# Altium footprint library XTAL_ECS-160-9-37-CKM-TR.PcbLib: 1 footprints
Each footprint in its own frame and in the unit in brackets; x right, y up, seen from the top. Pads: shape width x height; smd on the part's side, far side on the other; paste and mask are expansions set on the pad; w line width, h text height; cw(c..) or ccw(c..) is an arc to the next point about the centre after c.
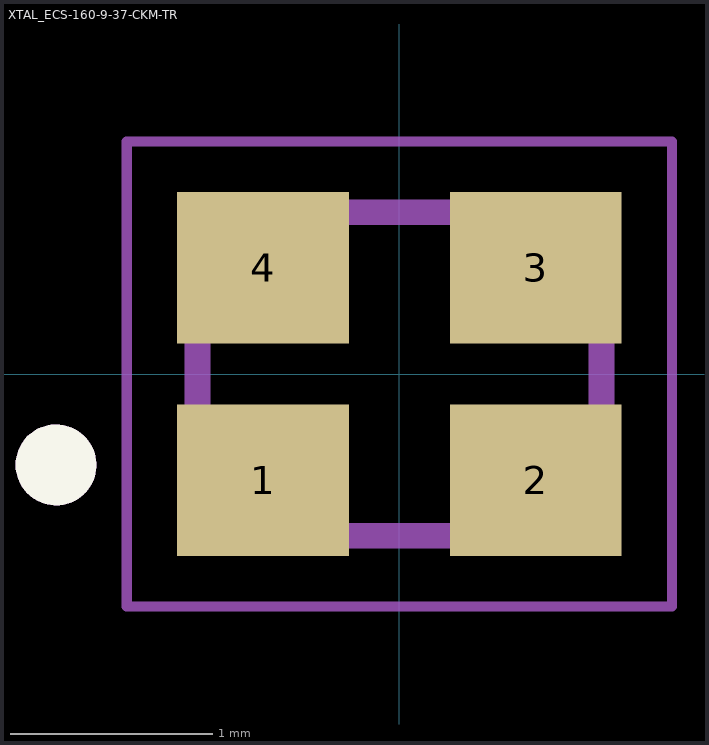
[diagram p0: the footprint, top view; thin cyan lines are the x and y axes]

## XTAL_ECS-160-9-37-CKM-TR [mm]
pads (4):
  rect 0.85x0.75 smd: 1(-0.675,-0.525) 2(0.675,-0.525) 3(0.675,0.525) 4(-0.675,0.525)
Top Overlay:
  circle w0.2: c-1.7,-0.45 r0.1
Mechanical 13:
  circle w0.2: c-1.7,-0.45 r0.1
  lines w0.127: -1,-0.8 -1,0.8 1,0.8 1,-0.8 -1,-0.8
Mechanical 15:
  lines w0.05: -1.35,-1.15 -1.35,1.15 1.35,1.15 1.35,-1.15 -1.35,-1.15
3D body "step_temp.STEP": height 0.55, standoff 0, extent -1,-0.8 1,0.8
